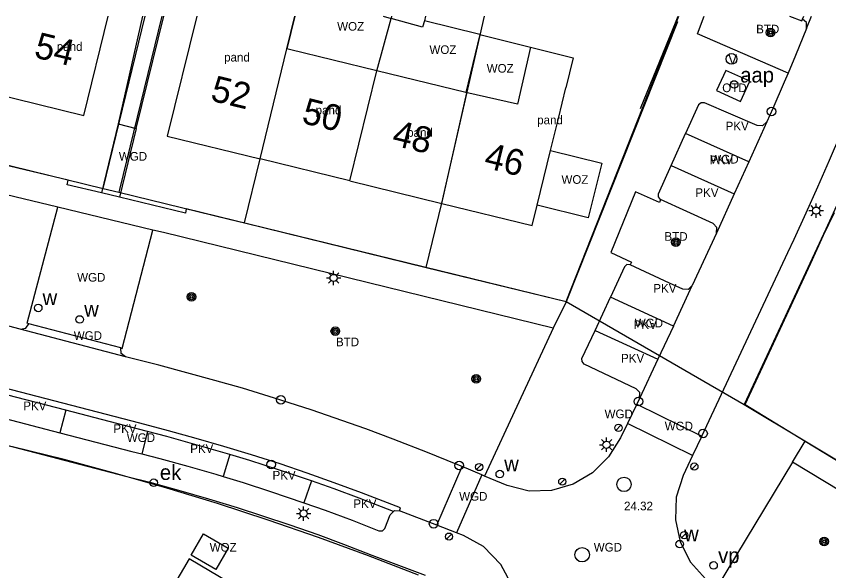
# Model space of a CAD drawing. Extents: x 198240 to 198429, y 356553 to 356721.
# Drawn here: x 198270.3 to 198326.7, y 356682.2 to 356720.6 of the extents above; entities that cross this region are included whole.
import ezdxf

# ---------------------------------------------------------------- set-up
doc = ezdxf.new("R2010")
doc.units = 0
for name, color, linetype in [('Afsluitpaal', 7, 'Continuous'), ('Afval apart plaats', 7, 'Continuous'), ('afval apartplaats lijn', 7, 'Continuous'), ('Afvalbak', 7, 'Continuous'), ('begroeid terreindeel kenmerkpunt', 7, 'Continuous'), ('Benzineput_olieput', 7, 'Continuous'), ('bijgebouw', 7, 'Continuous'), ('BOOM', 7, 'Continuous'), ('Elektrakast', 7, 'Continuous'), ('Grens beheer openbare ruimte wegbeheer', 7, 'Continuous'), ('grens individueel parkeervak', 7, 'Continuous'), ('Grens maaiveld', 7, 'Continuous'), ('grens WOZ object', 7, 'Continuous'), ('hoofdgebouw', 7, 'Continuous'), ('Hoogtepunt', 7, 'Continuous'), ('huisnummerreeks BGT', 7, 'Continuous'), ('identificerend kenmerkpunt pand', 7, 'Continuous'), ('identificerend kenmerkpunt parkeervak', 7, 'Continuous'), ('identificerend kenmerkpunt WOZ object', 7, 'Continuous'), ('Inspectieput_rioolput', 7, 'Continuous'), ('kant verharding', 7, 'Continuous'), ('kolk', 7, 'Continuous'), ('LICHTMAST', 7, 'Continuous'), ('onbegroeid terreindeel kenmerkpunt', 7, 'Continuous'), ('perceelsgrens_definitief', 7, 'Continuous'), ('raster geen IMGeo', 7, 'Continuous'), ('schutting geen IMGeo', 7, 'Continuous'), ('tussenmuur', 7, 'Continuous'), ('tussenmuur bijgebouw (GBKN Zuid)', 7, 'Continuous'), ('vlakafsluiter', 7, 'Continuous'), ('waterleidingput', 7, 'Continuous'), ('wegdeel kenmerkpunt', 7, 'Continuous'), ('weginrichtingselement lijn', 7, 'Continuous')]:
    doc.layers.add(name, color=color, linetype=linetype)

msp = doc.modelspace()

# ---------------------------------------------------------------- linework, layer by layer
at = {"layer": 'Afsluitpaal'}
for p, q in [((198312.26, 356692.276), (198311.91, 356691.919)), ((198302.593, 356689.558), (198302.243, 356689.201)), ((198317.526, 356689.589), (198317.176, 356689.232)), ((198308.362, 356688.545), (198308.012, 356688.188)), ((198300.504, 356684.735), (198300.154, 356684.378)), ((198316.819, 356684.835), (198316.469, 356684.478))]:
    msp.add_line(p, q, dxfattribs=at)
for centre in [(198312.087, 356692.096), (198302.42, 356689.378), (198317.353, 356689.409), (198308.189, 356688.365), (198316.646, 356684.655), (198300.331, 356684.555)]:
    msp.add_circle(centre, 0.25, dxfattribs=at)
at = {"layer": 'Afval apart plaats'}
msp.add_circle((198320.115, 356715.9), 0.263, dxfattribs=at)
msp.add_circle((198320.115, 356715.9), 0.263, dxfattribs=at)
at = {"layer": 'afval apartplaats lijn'}
msp.add_lwpolyline([(198319.525, 356716.869), (198318.892, 356715.472), (198320.561, 356714.717), (198321.194, 356716.12), (198319.525, 356716.869)], dxfattribs=at)
at = {"layer": 'Afvalbak'}
msp.add_circle((198319.93, 356717.671), 0.375, dxfattribs=at)
msp.add_circle((198319.93, 356717.671), 0.375, dxfattribs=at)
at = {"layer": 'Benzineput_olieput'}
msp.add_circle((198318.683, 356682.563), 0.263, dxfattribs=at)
msp.add_circle((198318.683, 356682.563), 0.263, dxfattribs=at)
at = {"layer": 'bijgebouw'}
for points in [[(198295.772, 356720.628), (198296.311, 356720.48)], [(198298.621, 356720.319), (198298.499, 356719.877), (198296.311, 356720.48)], [(198298.706, 356720.628), (198298.621, 356720.319)]]:
    msp.add_lwpolyline(points, dxfattribs=at)
at = {"layer": 'BOOM'}
for centre, radius in [((198322.644, 356719.505), 0.3), ((198322.644, 356719.505), 0.2), ((198322.644, 356719.505), 0.1), ((198316.076, 356704.97), 0.3), ((198316.076, 356704.97), 0.2), ((198316.076, 356704.97), 0.1), ((198282.466, 356701.176), 0.3), ((198282.466, 356701.176), 0.2), ((198282.466, 356701.176), 0.1), ((198292.444, 356698.794), 0.3), ((198292.444, 356698.794), 0.2), ((198292.444, 356698.794), 0.1), ((198302.223, 356695.491), 0.3), ((198302.223, 356695.491), 0.2), ((198302.223, 356695.491), 0.1), ((198326.354, 356684.216), 0.3), ((198326.354, 356684.216), 0.2), ((198326.354, 356684.216), 0.1)]:
    msp.add_circle(centre, radius, dxfattribs=at)
at = {"layer": 'Elektrakast'}
msp.add_circle((198279.844, 356688.292), 0.263, dxfattribs=at)
msp.add_circle((198279.844, 356688.292), 0.263, dxfattribs=at)
at = {"layer": 'Grens beheer openbare ruimte wegbeheer'}
for p, q in [((198317.228, 356690.174), (198312.707, 356692.395)), ((198302.614, 356688.831), (198300.854, 356684.816))]:
    msp.add_line(p, q, dxfattribs=at)
at = {"layer": 'grens individueel parkeervak'}
for p, q in [((198321.129, 356710.546), (198316.748, 356712.505)), ((198315.749, 356710.288), (198320.122, 356708.309)), ((198315.897, 356699.152), (198311.531, 356701.163)), ((198310.46, 356698.854), (198314.828, 356696.863)), ((198273.74, 356693.315), (198273.335, 356691.761)), ((198279.416, 356691.839), (198279.016, 356690.284)), ((198285.119, 356690.238), (198284.674, 356688.719)), ((198290.786, 356688.423), (198290.255, 356686.898))]:
    msp.add_line(p, q, dxfattribs=at)
at = {"layer": 'Grens maaiveld'}
for p, q in [((198278.625, 356712.851), (198277.473, 356708.079)), ((198279.794, 356705.809), (198273.184, 356707.397)), ((198313.366, 356693.731), (198317.861, 356691.51)), ((198299.476, 356685.349), (198301.251, 356689.407))]:
    msp.add_line(p, q, dxfattribs=at)
for points in [[(198316.096, 356720.28), (198316.239, 356720.628)], [(198319.525, 356716.869), (198318.892, 356715.472), (198320.561, 356714.717), (198321.194, 356716.12), (198319.525, 356716.869)], [(198296.898, 356686.347), (198296.977, 356686.555), (198294.265, 356687.594), (198292.374, 356688.291), (198290.5, 356688.957), (198288.618, 356689.597), (198286.63, 356690.219), (198284.719, 356690.8), (198282.78, 356691.357), (198280.86, 356691.889), (198278.876, 356692.409), (198239.787, 356702.57)]]:
    msp.add_lwpolyline(points, dxfattribs=at)
at = {"layer": 'grens WOZ object'}
for p, q in [((198289.087, 356718.381), (198289.638, 356720.628)), ((198295.313, 356716.856), (198296.311, 356720.48)), ((198302.467, 356719.373), (198298.621, 356720.319)), ((198302.467, 356719.373), (198301.491, 356715.342)), ((198302.467, 356719.373), (198305.975, 356718.478)), ((198305.975, 356718.478), (198305.073, 356714.523)), ((198305.073, 356714.523), (198301.491, 356715.342)), ((198282.436, 356683.277), (198283.309, 356684.759)), ((198283.309, 356684.759), (198285.02, 356683.751)), ((198285.02, 356683.751), (198284.147, 356682.269)), ((198284.147, 356682.269), (198282.436, 356683.277))]:
    msp.add_line(p, q, dxfattribs=at)
msp.add_lwpolyline([(198307.371, 356711.312), (198310.923, 356710.436), (198309.992, 356706.659), (198306.447, 356707.533)], dxfattribs=at)
at = {"layer": 'hoofdgebouw'}
for p, q in [((198289.638, 356720.628), (198289.087, 356718.381)), ((198289.273, 356718.335), (198289.087, 356718.381)), ((198295.313, 356716.856), (198289.273, 356718.335)), ((198301.491, 356715.342), (198295.313, 356716.856)), ((198307.918, 356713.55), (198308.442, 356715.675)), ((198307.371, 356711.312), (198307.918, 356713.55)), ((198306.447, 356707.533), (198307.371, 356711.312)), ((198293.448, 356709.22), (198287.222, 356710.746)), ((198293.448, 356709.22), (198299.83, 356707.657))]:
    msp.add_line(p, q, dxfattribs=at)
for points in [[(198268.598, 356715.31), (198274.994, 356713.745), (198276.678, 356720.628)], [(198282.834, 356720.628), (198280.783, 356712.323), (198287.222, 356710.746)], [(198305.975, 356718.478), (198305.073, 356714.523), (198301.491, 356715.342)], [(198305.975, 356718.478), (198308.95, 356717.746), (198308.442, 356715.675)], [(198299.83, 356707.657), (198306.101, 356706.12), (198306.447, 356707.533)], [(198286.857, 356673.34), (198288.512, 356676.123), (198287.308, 356676.825), (198288.741, 356679.209), (198282.309, 356683.018), (198279.246, 356677.817)]]:
    msp.add_lwpolyline(points, dxfattribs=at)
at = {"layer": 'Inspectieput_rioolput'}
for centre in [(198312.473, 356688.177), (198309.567, 356683.301)]:
    msp.add_circle(centre, 0.5, dxfattribs=at)
at = {"layer": 'kant verharding'}
for p, q in [((198279.062, 356720.628), (198277.383, 356713.161)), ((198278.625, 356712.851), (198280.543, 356720.628)), ((198324.853, 356720.417), (198324.937, 356720.628)), ((198325.141, 356719.773), (198325.48, 356720.628)), ((198277.383, 356713.161), (198276.227, 356708.377)), ((198322.377, 356713.318), (198321.129, 356710.546)), ((198315.749, 356710.288), (198316.748, 356712.505)), ((198321.129, 356710.546), (198320.122, 356708.309)), ((198277.473, 356708.079), (198276.227, 356708.377)), ((198320.122, 356708.309), (198318.897, 356705.588)), ((198318.897, 356705.588), (198317.204, 356701.952)), ((198270.578, 356698.941), (198256.096, 356702.725)), ((198315.897, 356699.152), (198317.204, 356701.952)), ((198310.46, 356698.854), (198311.531, 356701.163)), ((198277.554, 356697.633), (198271.178, 356699.303)), ((198307.556, 356698.996), (198302.787, 356688.756)), ((198315.897, 356699.152), (198314.828, 356696.863)), ((198277.897, 356697.027), (198270.578, 356698.941)), ((198314.828, 356696.863), (198313.555, 356694.136)), ((198273.74, 356693.315), (198268.06, 356694.794)), ((198313.555, 356694.136), (198313.366, 356693.731)), ((198313.366, 356693.731), (198312.707, 356692.395)), ((198320.873, 356693.711), (198325.044, 356691.174)), ((198267.689, 356693.232), (198273.335, 356691.761)), ((198317.861, 356691.51), (198317.228, 356690.174)), ((198302.614, 356688.831), (198301.251, 356689.407)), ((198324.168, 356689.714), (198318.94, 356681.083)), ((198302.787, 356688.756), (198302.614, 356688.831)), ((198299.476, 356685.349), (198296.898, 356686.347)), ((198300.854, 356684.816), (198299.476, 356685.349))]:
    msp.add_line(p, q, dxfattribs=at)
for points in [[(198323.856, 356716.689), (198317.58, 356719.414), (198318.042, 356720.628)], [(198323.945, 356720.628), (198324.813, 356720.306), (198324.853, 356720.417)], [(198325.141, 356719.773), (198325.121, 356720.188), (198324.853, 356720.417)], [(198316.096, 356720.28), (198316.184, 356720.236), (198308.454, 356700.838)], [(198325.141, 356719.773), (198324.38, 356717.918), (198323.856, 356716.689)], [(198317.861, 356691.51), (198323.84, 356704.262), (198324.269, 356705.183), (198325.106, 356706.997), (198325.925, 356708.813), (198326.734, 356710.653), (198327.521, 356712.488), (198328.316, 356714.335), (198329.102, 356716.178), (198329.869, 356718.018)], [(198276.227, 356708.377), (198273.833, 356708.949), (198273.906, 356709.256), (198243.052, 356716.618), (198242.98, 356716.333), (198239.787, 356717.12)], [(198323.856, 356716.689), (198323.592, 356716.07), (198322.793, 356714.232), (198322.377, 356713.318)], [(198322.377, 356713.318), (198322.088, 356713.037), (198321.711, 356713.05), (198318.052, 356714.635), (198317.816, 356714.631), (198317.645, 356714.495), (198316.748, 356712.505)], [(198273.184, 356707.397), (198258.258, 356710.969), (198256.096, 356702.725)], [(198315.015, 356707.917), (198314.875, 356708.11), (198314.858, 356708.312), (198315.749, 356710.288)], [(198308.454, 356700.838), (198282.106, 356707.275), (198282.045, 356706.986), (198277.473, 356708.079)], [(198315.015, 356707.917), (198314.936, 356707.728), (198313.262, 356708.468), (198311.562, 356704.246), (198312.987, 356703.577), (198312.904, 356703.399)], [(198318.897, 356705.588), (198318.916, 356705.983), (198318.665, 356706.257), (198315.015, 356707.917)], [(198271.178, 356699.303), (198271.067, 356699.349), (198273.184, 356707.397)], [(198320.873, 356693.711), (198325.431, 356703.505), (198326.306, 356705.459), (198327.071, 356707.032)], [(198277.554, 356697.633), (198277.651, 356697.593), (198279.794, 356705.809)], [(198307.556, 356698.996), (198280.518, 356705.637), (198279.794, 356705.809)], [(198312.904, 356703.399), (198312.658, 356703.411), (198312.503, 356703.26), (198311.531, 356701.163)], [(198317.204, 356701.952), (198316.933, 356701.696), (198316.545, 356701.699), (198315.634, 356702.131), (198312.904, 356703.399)], [(198270.578, 356698.941), (198270.981, 356699.006), (198271.178, 356699.303)], [(198239.787, 356698.674), (198277.877, 356688.756), (198279.573, 356688.328), (198281.722, 356687.74), (198283.655, 356687.172), (198285.635, 356686.576), (198287.401, 356686.002), (198289.29, 356685.363), (198291.23, 356684.694), (198293.016, 356684.031), (198294.971, 356683.265), (198298.672, 356681.879)], [(198313.555, 356694.136), (198313.566, 356694.536), (198313.312, 356694.8), (198309.708, 356696.509), (198309.571, 356696.697), (198309.554, 356696.899), (198310.46, 356698.854)], [(198277.897, 356697.027), (198277.584, 356697.255), (198277.554, 356697.633)], [(198301.251, 356689.407), (198300.833, 356689.584), (198298.839, 356690.386), (198296.446, 356691.315), (198294.564, 356692.017), (198290.779, 356693.336), (198288.22, 356694.16), (198286.011, 356694.839), (198284.087, 356695.381), (198280.207, 356696.433), (198277.897, 356697.027)], [(198279.416, 356691.839), (198278.778, 356692.003), (198273.74, 356693.315)], [(198312.707, 356692.395), (198312.223, 356691.413), (198311.406, 356690.088), (198310.297, 356688.979), (198308.944, 356688.181), (198307.446, 356687.741), (198305.889, 356687.704), (198304.368, 356688.092), (198302.787, 356688.756)], [(198273.335, 356691.761), (198278.322, 356690.462), (198279.016, 356690.284)], [(198285.119, 356690.238), (198282.701, 356690.947), (198280.765, 356691.492), (198279.416, 356691.839)], [(198325.044, 356691.174), (198339.161, 356682.588), (198341.279, 356681.288), (198343.379, 356680.014), (198351.339, 356675.001), (198352.823, 356674.056), (198356.526, 356671.657), (198358.554, 356670.367), (198359.064, 356670.025)], [(198279.016, 356690.284), (198280.266, 356689.963), (198282.21, 356689.432), (198284.148, 356688.879), (198284.674, 356688.719)], [(198290.786, 356688.423), (198290.38, 356688.565), (198288.492, 356689.195), (198286.518, 356689.828), (198285.119, 356690.238)], [(198317.228, 356690.174), (198316.569, 356688.783), (198316.101, 356687.293), (198316.037, 356685.727), (198316.368, 356684.197), (198317.077, 356682.795), (198318.116, 356681.632), (198318.297, 356681.511)], [(198333.616, 356672.898), (198338.593, 356680.997), (198324.168, 356689.714)], [(198284.674, 356688.719), (198286.047, 356688.303), (198287.953, 356687.692), (198290.255, 356686.898)], [(198296.486, 356686.29), (198294.087, 356687.227), (198292.368, 356687.872), (198290.786, 356688.423)], [(198290.255, 356686.898), (198291.737, 356686.387), (198293.617, 356685.688), (198295.469, 356684.947), (198295.71, 356684.961), (198295.87, 356685.129), (198296.252, 356686.058), (198296.486, 356686.29)], [(198296.486, 356686.29), (198296.555, 356686.359), (198296.898, 356686.347)], [(198304.947, 356677.77), (198305.092, 356679.489), (198304.764, 356681.085), (198303.938, 356682.621), (198302.718, 356683.87), (198301.331, 356684.631), (198300.854, 356684.816)]]:
    msp.add_lwpolyline(points, dxfattribs=at)
at = {"layer": 'kolk'}
for centre in [(198322.705, 356714.019), (198288.672, 356694.035), (198313.467, 356693.928), (198317.953, 356691.707), (198287.995, 356689.552), (198301.038, 356689.491), (198299.266, 356685.449)]:
    msp.add_circle(centre, 0.3, dxfattribs=at)
at = {"layer": 'LICHTMAST'}
for p, q in [((198325.624, 356707.332), (198325.447, 356707.509)), ((198325.801, 356707.405), (198325.801, 356707.655)), ((198325.978, 356707.332), (198326.155, 356707.509)), ((198325.301, 356707.155), (198325.551, 356707.155)), ((198325.447, 356706.801), (198325.624, 356706.978)), ((198325.801, 356706.655), (198325.801, 356706.905)), ((198326.155, 356706.801), (198325.978, 356706.978)), ((198326.051, 356707.155), (198326.301, 356707.155)), ((198292.328, 356702.735), (198292.328, 356702.985)), ((198291.828, 356702.485), (198292.078, 356702.485)), ((198292.151, 356702.662), (198291.974, 356702.839)), ((198292.505, 356702.662), (198292.682, 356702.839)), ((198292.578, 356702.485), (198292.828, 356702.485)), ((198291.974, 356702.131), (198292.151, 356702.308)), ((198292.328, 356701.985), (198292.328, 356702.235)), ((198292.682, 356702.131), (198292.505, 356702.308)), ((198311.085, 356691.099), (198310.908, 356691.276)), ((198311.262, 356691.172), (198311.262, 356691.422)), ((198311.439, 356691.099), (198311.616, 356691.276)), ((198310.762, 356690.922), (198311.012, 356690.922)), ((198310.908, 356690.568), (198311.085, 356690.745)), ((198311.262, 356690.422), (198311.262, 356690.672)), ((198311.616, 356690.568), (198311.439, 356690.745)), ((198311.512, 356690.922), (198311.762, 356690.922)), ((198290.244, 356686.402), (198290.244, 356686.652)), ((198289.744, 356686.152), (198289.994, 356686.152)), ((198290.067, 356686.329), (198289.89, 356686.506)), ((198290.421, 356686.329), (198290.598, 356686.506)), ((198290.494, 356686.152), (198290.744, 356686.152)), ((198289.89, 356685.798), (198290.067, 356685.975)), ((198290.244, 356685.652), (198290.244, 356685.902)), ((198290.598, 356685.798), (198290.421, 356685.975))]:
    msp.add_line(p, q, dxfattribs=at)
for centre in [(198325.801, 356707.155), (198292.328, 356702.485), (198311.262, 356690.922), (198290.244, 356686.152)]:
    msp.add_circle(centre, 0.25, dxfattribs=at)
at = {"layer": 'perceelsgrens_definitief'}
for points in [[(198276.34, 356708.694), (198279.261, 356720.628)], [(198280.398, 356720.628), (198277.469, 356708.608), (198277.425, 356708.429)], [(198286.135, 356706.297), (198287.222, 356710.746), (198289.087, 356718.381), (198289.636, 356720.628)], [(198298.75, 356703.2), (198299.833, 356707.669), (198302.79, 356720.628)], [(198308.457, 356700.864), (198316.269, 356720.628)], [(198332.837, 356720.628), (198331.931, 356718.35), (198330.183, 356714.16), (198328.366, 356709.999), (198326.48, 356705.869)], [(198267.469, 356710.864), (198276.34, 356708.694)], [(198276.34, 356708.694), (198277.425, 356708.429)], [(198277.425, 356708.429), (198285.082, 356706.556), (198286.135, 356706.297)], [(198286.135, 356706.297), (198298.75, 356703.2)], [(198326.48, 356705.869), (198320.807, 356693.703)], [(198298.75, 356703.2), (198308.457, 356700.864)], [(198308.457, 356700.864), (198320.807, 356693.703)], [(198320.807, 356693.703), (198329.236, 356688.676)], [(198298.205, 356681.89), (198294.757, 356683.22), (198291.286, 356684.488), (198287.793, 356685.695), (198284.279, 356686.84), (198280.746, 356687.922), (198277.194, 356688.941), (198273.624, 356689.897), (198270.038, 356690.79)]]:
    msp.add_lwpolyline(points, dxfattribs=at)
at = {"layer": 'raster geen IMGeo'}
msp.add_line((198278.625, 356712.851), (198277.473, 356708.079), dxfattribs=at)
at = {"layer": 'schutting geen IMGeo'}
msp.add_line((198313.614, 356714.233), (198316.096, 356720.28), dxfattribs=at)
msp.add_lwpolyline([(198316.096, 356720.28), (198316.239, 356720.628)], dxfattribs=at)
at = {"layer": 'tussenmuur'}
for p, q in [((198287.222, 356710.746), (198289.087, 356718.381)), ((198293.448, 356709.22), (198295.313, 356716.856))]:
    msp.add_line(p, q, dxfattribs=at)
msp.add_lwpolyline([(198299.83, 356707.657), (198301.579, 356715.32), (198301.491, 356715.342)], dxfattribs=at)
at = {"layer": 'tussenmuur bijgebouw (GBKN Zuid)'}
msp.add_line((198296.352, 356720.628), (198296.311, 356720.48), dxfattribs=at)
at = {"layer": 'vlakafsluiter'}
for p, q in [((198277.383, 356713.161), (198278.625, 356712.851)), ((198308.454, 356700.838), (198307.556, 356698.996)), ((198324.168, 356689.714), (198325.044, 356691.174))]:
    msp.add_line(p, q, dxfattribs=at)
at = {"layer": 'waterleidingput'}
for centre in [(198271.831, 356700.407), (198271.831, 356700.407), (198274.716, 356699.607), (198274.716, 356699.607), (198303.856, 356688.889), (198303.856, 356688.889), (198316.339, 356684.032), (198316.339, 356684.032)]:
    msp.add_circle(centre, 0.263, dxfattribs=at)
at = {"layer": 'weginrichtingselement lijn'}
msp.add_lwpolyline([(198296.898, 356686.347), (198296.977, 356686.555), (198294.265, 356687.594), (198292.374, 356688.291), (198290.5, 356688.957), (198288.618, 356689.597), (198286.63, 356690.219), (198284.719, 356690.8), (198282.78, 356691.357), (198280.86, 356691.889), (198278.876, 356692.409), (198239.787, 356702.57)], dxfattribs=at)

# ---------------------------------------------------------------- texts
at = {"layer": 'Afval apart plaats'}
msp.add_text('aap', height=1.05, dxfattribs=at).set_placement((198320.535, 356716.033))
at = {"layer": 'Afvalbak'}
msp.add_text('V', height=0.686, dxfattribs=at).set_placement((198319.702, 356717.3))
msp.add_text('V', height=0.686, dxfattribs=at).set_placement((198319.702, 356717.3))
at = {"layer": 'begroeid terreindeel kenmerkpunt'}
for p in [(198321.639, 356719.439), (198315.279, 356705.064), (198292.489, 356697.752)]:
    msp.add_text('BTD', height=0.6, dxfattribs=at).set_placement(p)
at = {"layer": 'Benzineput_olieput'}
msp.add_text('vp', height=1.05, dxfattribs=at).set_placement((198319.003, 356682.724))
at = {"layer": 'Elektrakast'}
msp.add_text('ek', height=1.05, dxfattribs=at).set_placement((198280.273, 356688.483))
at = {"layer": 'Hoogtepunt'}
msp.add_text('24.32', height=0.6, dxfattribs=at).set_placement((198312.473, 356686.377))
msp.add_text('24.32', height=0.6, dxfattribs=at).set_placement((198312.473, 356686.377))
at = {"layer": 'huisnummerreeks BGT'}
for s, rotation, p in [('54', 346.3, (198271.472, 356717.798)), ('52', 346.2, (198283.71, 356714.799)), ('50', 346.2, (198290.042, 356713.247)), ('48', 346.2, (198296.302, 356711.714)), ('46', 346.2, (198302.685, 356710.15))]:
    msp.add_text(s, height=1.8, rotation=rotation, dxfattribs=at).set_placement(p)
at = {"layer": 'identificerend kenmerkpunt pand'}
for p in [(198273.118, 356718.23), (198284.728, 356717.49), (198291.078, 356713.82), (198306.448, 356713.14), (198297.428, 356712.27)]:
    msp.add_text('pand', height=0.6, dxfattribs=at).set_placement(p)
at = {"layer": 'identificerend kenmerkpunt parkeervak'}
for p in [(198319.521, 356712.717), (198318.42, 356710.359), (198317.422, 356708.104), (198314.505, 356701.472), (198313.144, 356698.939), (198312.266, 356696.625), (198270.793, 356693.32), (198277.05, 356691.742), (198282.376, 356690.359), (198288.087, 356688.514), (198293.695, 356686.541)]:
    msp.add_text('PKV', height=0.6, dxfattribs=at).set_placement(p)
at = {"layer": 'identificerend kenmerkpunt WOZ object'}
for p in [(198292.572, 356719.628), (198298.974, 356718.014), (198302.945, 356716.719), (198308.133, 356709.012), (198283.728, 356683.514)]:
    msp.add_text('WOZ', height=0.6, dxfattribs=at).set_placement(p)
at = {"layer": 'onbegroeid terreindeel kenmerkpunt'}
msp.add_text('OTD', height=0.6, dxfattribs=at).set_placement((198319.286, 356715.368))
at = {"layer": 'waterleidingput'}
for p in [(198272.135, 356700.605), (198275.02, 356699.805), (198304.16, 356689.087), (198316.643, 356684.23)]:
    msp.add_text('w', height=1.05, dxfattribs=at).set_placement(p)
at = {"layer": 'wegdeel kenmerkpunt'}
for p in [(198277.427, 356710.617), (198318.46, 356710.42), (198274.533, 356702.232), (198313.219, 356699.059), (198274.299, 356698.191), (198311.124, 356692.763), (198315.296, 356691.918), (198277.978, 356691.116), (198301.035, 356687.046), (198310.373, 356683.52)]:
    msp.add_text('WGD', height=0.6, dxfattribs=at).set_placement(p)

doc.saveas('drawing.dxf')
